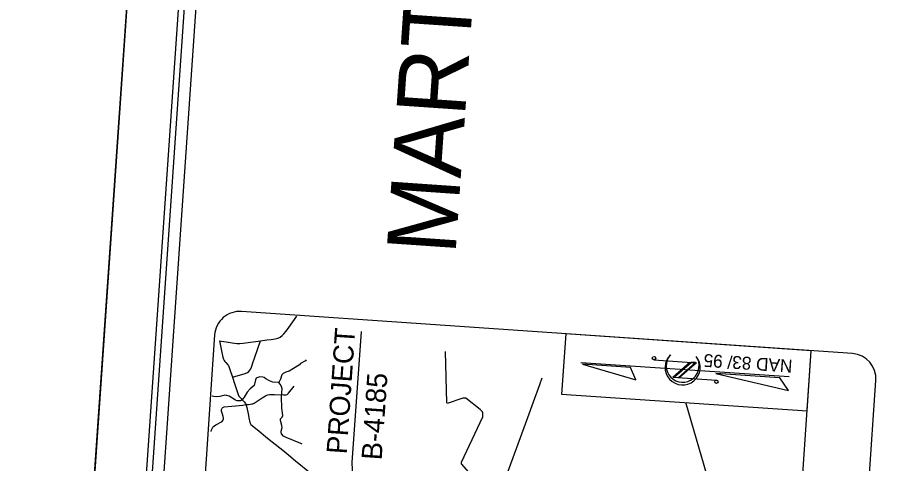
# Model space of a CAD drawing. Extents: x 2598107 to 2605763, y 726018 to 731166.
# Drawn here: x 2598107 to 2598961, y 728494 to 728931 of the extents above; entities that cross this region are included whole.
import ezdxf

# ---------------------------------------------------------------- set-up
doc = ezdxf.new("R2010")
doc.units = 0
for name, color, linetype in [('Old_Level_1', 7, 'Continuous'), ('Old_Level_32', 7, 'Continuous'), ('Old_Level_38', 7, 'Continuous'), ('Old_Level_50', 7, 'Continuous'), ('Old_Level_59', 7, 'Continuous'), ('Sheet Cutting Line CELL', 7, 'Continuous'), ('Sheet North Arrow CELL', 7, 'Continuous'), ('Sheet Plot Border Inside CELL', 7, 'Continuous'), ('Sheet Plot Border Outside CELL', 7, 'Continuous'), ('Sheet Title CELL', 7, 'Continuous')]:
    doc.layers.add(name, color=color, linetype=linetype)

msp = doc.modelspace()

# ---------------------------------------------------------------- linework, layer by layer
at = {"layer": 'Old_Level_1'}
for p, q in [((2598924.85, 728601.46), (2598326.15, 728642.69)), ((2598299.76, 728619.7), (2598252.58, 727934.77)), ((2598434.73, 728494.71), (2598443.56, 728622.92)), ((2598833.79, 727869.93), (2598884.37, 728604.25)), ((2598900.67, 727890.13), (2598947.84, 728575.07)), ((2598848.36, 728257.99), (2598761.39, 728553.37)), ((2598440.93, 728330.65), (2598434.73, 728494.71))]:
    msp.add_line(p, q, dxfattribs=at)
msp.add_lwpolyline([(2598880.3, 728545.18), (2598884.37, 728604.25), (2598643.92, 728620.81), (2598639.85, 728561.74)], close=True, dxfattribs=at)
for centre, start, end in [((2598324.45, 728618), 86.06002, 176.06012), ((2598923.15, 728576.77), 356.06009, 86.05999)]:
    msp.add_arc(centre, 24.75, start, end, dxfattribs=at)
at = {"layer": 'Old_Level_32'}
for points in [[(2598344.61, 728613.86), (2598350.88, 728614.78), (2598355.07, 728615.24), (2598359.28, 728615.93), (2598361.62, 728616.54), (2598362.73, 728617), (2598363.96, 728617.61), (2598365.88, 728619.08), (2598367.55, 728620.69), (2598369.79, 728623.49), (2598372.51, 728627.08), (2598376.51, 728632.4), (2598380.3, 728638.14)], [(2598304.42, 728613.76), (2598306.68, 728613.63), (2598311.13, 728612.96), (2598316.92, 728612.09), (2598321.52, 728611.4), (2598322.52, 728611.3), (2598324.54, 728611.3), (2598327.67, 728611.57), (2598344.61, 728613.86)], [(2598304.42, 728613.76), (2598306.98, 728602.41), (2598307.94, 728598.06), (2598308.47, 728595.87), (2598309.06, 728594.55), (2598309.74, 728593.57), (2598310.62, 728592.71), (2598312.66, 728590.52), (2598313.27, 728589.67), (2598313.72, 728588.61), (2598314.71, 728585.82), (2598317.33, 728578.42)], [(2598317.33, 728578.42), (2598329.85, 728582.06), (2598331.92, 728583.05), (2598333.19, 728583.88), (2598334.31, 728585.09), (2598335.29, 728586.59), (2598335.97, 728588.06), (2598336.69, 728589.98), (2598337.38, 728592.33), (2598338.97, 728596.83), (2598342.23, 728606.43), (2598344.61, 728613.86)], [(2598317.33, 728578.42), (2598319.42, 728572.24), (2598321.59, 728565.2), (2598322.79, 728561.2), (2598323.51, 728559.79), (2598324.11, 728559), (2598325.33, 728557.7), (2598328.9, 728554.15), (2598329.9, 728552.63), (2598330.49, 728551.4)], [(2598547.02, 728377.16), (2598555.75, 728400.72), (2598559.16, 728409.89), (2598561.04, 728415.07), (2598566.86, 728430.79), (2598569.08, 728436.86), (2598574.79, 728452.16), (2598576.64, 728457.17), (2598578.83, 728463.18), (2598590.03, 728493.53), (2598606.66, 728538.81), (2598612.3, 728554.06), (2598618.6, 728570.97), (2598620.87, 728577.51)], [(2598330.49, 728551.4), (2598333.03, 728551.56), (2598335.09, 728551.84), (2598336.3, 728552.04), (2598337.32, 728552.32), (2598338.52, 728552.97), (2598340.45, 728554.28), (2598346.32, 728558.19), (2598349.49, 728560.17), (2598350.89, 728560.72), (2598351.99, 728561), (2598353.69, 728561.22), (2598355.81, 728561.24), (2598358.45, 728561.32), (2598367.22, 728561.15), (2598368.56, 728561.06), (2598369.42, 728561.02), (2598369.88, 728561.14), (2598370.79, 728561.46), (2598371.13, 728561.66), (2598371.62, 728562.06), (2598372.08, 728562.48), (2598377.71, 728569.5)], [(2598296.26, 728524.99), (2598296.78, 728526.88), (2598297.31, 728528.05), (2598297.79, 728528.75), (2598298.16, 728529.32), (2598298.84, 728530.12), (2598301.11, 728531.62), (2598307.04, 728534.93), (2598307.7, 728535.72), (2598308.14, 728536.54), (2598308.38, 728537.45), (2598308.36, 728538.25), (2598308.03, 728539.69), (2598307.38, 728541.94), (2598306.54, 728544.85), (2598306.42, 728545.58), (2598306.61, 728546.6), (2598306.87, 728547.36), (2598307.31, 728547.99), (2598307.8, 728548.46), (2598308.43, 728548.82), (2598309.08, 728549.12), (2598316.7, 728549.85), (2598327.31, 728550.93), (2598330.49, 728551.4)], [(2598330.49, 728551.4), (2598331.2, 728548.76), (2598332.51, 728542.36), (2598333.66, 728536.72), (2598334.16, 728534.3), (2598334.65, 728533.18), (2598335.4, 728532.04), (2598336.55, 728530.94), (2598338.49, 728529.47), (2598341.63, 728526.93), (2598351.7, 728518.69), (2598363.54, 728509.09), (2598366.47, 728506.77), (2598372.45, 728501.83), (2598379.03, 728496.45), (2598394.3, 728483.96)]]:
    msp.add_lwpolyline(points, dxfattribs=at)
at = {"layer": 'Old_Level_50'}
msp.add_line((2598327, 728556.17), (2598327, 728556.17), dxfattribs=at)
at = {"layer": 'Old_Level_59'}
for points in [[(2598552.49, 728481.18), (2598551.22, 728482.5), (2598541.65, 728493.26), (2598541.85, 728495.14), (2598562.61, 728539.34), (2598562.68, 728543.24), (2598562.25, 728544.4), (2598560.11, 728546.63), (2598545.85, 728557.61), (2598542.9, 728557.75), (2598527.83, 728552.67), (2598527.29, 728553.32), (2598526.19, 728603.46)], [(2598389.62, 728595.24), (2598388.99, 728594.29), (2598383.94, 728591.64), (2598382.83, 728590.56), (2598377.17, 728586.67), (2598372.88, 728584.23), (2598369.71, 728583.37), (2598368.85, 728582.78), (2598367.04, 728581.99), (2598365.78, 728580.65), (2598364.48, 728576.45), (2598362.64, 728573.13)], [(2598362.64, 728573.13), (2598356.83, 728573.28), (2598353.54, 728574.57), (2598349.95, 728576.75), (2598348.34, 728577.95), (2598347.04, 728578.39), (2598343.95, 728578.54), (2598341.07, 728577.79), (2598340.44, 728577.19), (2598339.78, 728575.71), (2598338.95, 728571.34), (2598338.45, 728570.24), (2598334.68, 728566.89), (2598331.77, 728563.62), (2598328.8, 728558.61), (2598326.66, 728556.07), (2598325.18, 728555.01), (2598321.95, 728555.15), (2598320.09, 728555.75), (2598313.96, 728559.56), (2598311.83, 728560.28), (2598309.68, 728560.64), (2598308.97, 728560.41), (2598307.18, 728560.13), (2598304.76, 728559.36), (2598301.89, 728559), (2598299.13, 728559.25), (2598297.44, 728559.86)], [(2598385.57, 728512.78), (2598384.42, 728513.36), (2598369.77, 728519.07), (2598367.23, 728520.45), (2598365.43, 728522.68), (2598365.06, 728524.58), (2598364.95, 728525.46), (2598365.85, 728528.94), (2598365.59, 728531.09), (2598364.28, 728535.8), (2598364.47, 728537.44), (2598366.11, 728539.12), (2598366.77, 728540.73), (2598365.58, 728547.95), (2598365.41, 728559.04), (2598365.92, 728566.81), (2598365.34, 728569.24), (2598364, 728571.43), (2598362.64, 728573.13)]]:
    msp.add_lwpolyline(points, dxfattribs=at)
at = {"layer": 'Sheet Cutting Line CELL'}
msp.add_line((2598106.57, 727386.04), (2598366.91, 731166.08), dxfattribs=at)
at = {"layer": 'Sheet North Arrow CELL'}
for p, q in [((2598746.24, 728600.06), (2598746.41, 728600.27)), ((2598862.89, 728578.58), (2598658.61, 728592.47)), ((2598730.23, 728595.34), (2598772.15, 728592.49)), ((2598765.61, 728592.93), (2598748.93, 728578.37)), ((2598767.15, 728592.83), (2598750.47, 728578.27)), ((2598770.99, 728592.57), (2598754.31, 728578.01)), ((2598754.31, 728578.01), (2598770.99, 728592.57)), ((2598772.15, 728592.49), (2598755.47, 728577.93)), ((2598770.99, 728592.57), (2598767.15, 728592.83)), ((2598748.93, 728578.37), (2598791.55, 728575.48)), ((2598750.47, 728578.27), (2598754.31, 728578.01))]:
    msp.add_line(p, q, dxfattribs=at)
for points in [[(2598660.31, 728590.93), (2598712.57, 728575.67), (2598707.45, 728587.73)], [(2598790.81, 728581.81), (2598861.99, 728565.35), (2598853.66, 728577.54)]]:
    msp.add_lwpolyline(points, close=True, dxfattribs=at)
for centre in [(2598730.37, 728597), (2598791.5, 728573.81)]:
    msp.add_circle(centre, 1.67, dxfattribs=at)
for centre, radius, start, end in [((2598758.35, 728587.87), 17.2, 133.95087, 38.50491), ((2598758.45, 728589.53), 16.12, 139.20589, 34.73956)]:
    msp.add_arc(centre, radius, start, end, dxfattribs=at)
at = {"layer": 'Sheet Plot Border Inside CELL'}
msp.add_lwpolyline([(2600527.34, 727248.63), (2600784.97, 730989.4), (2598416.61, 731152.51), (2598158.97, 727411.75)], close=True, dxfattribs=at)
at = {"layer": 'Sheet Plot Border Outside CELL'}
msp.add_lwpolyline([(2598366.91, 731166.08), (2598106.57, 727386.04), (2600575.69, 727215.98), (2600836.03, 730996.03)], close=True, dxfattribs=at)
at = {"layer": 'Sheet Title CELL'}
for points in [[(2598418.85, 731101.64), (2598190.02, 727779.46)], [(2598429.3, 731089.62), (2598209.78, 727902.2)]]:
    msp.add_lwpolyline(points, dxfattribs=at)

# ---------------------------------------------------------------- texts
at = {"layer": 'Old_Level_1'}
for s, p in [('PROJECT', (2598429.16, 728502.51)), ('B-4185', (2598463.43, 728496.65))]:
    msp.add_text(s, height=19.8, rotation=86.06011, dxfattribs=at).set_placement(p)
at = {"layer": 'Old_Level_38'}
msp.add_text('        MARTIN COUNTY        ', height=67.5, rotation=86.06011, dxfattribs=at).set_placement((2598521.95, 728497.41))
at = {"layer": 'Sheet North Arrow CELL'}
msp.add_text('NAD 83/ 95', height=12.6, rotation=176.11085, dxfattribs=at).set_placement((2598866.34, 728595.24))

doc.saveas('drawing.dxf')
